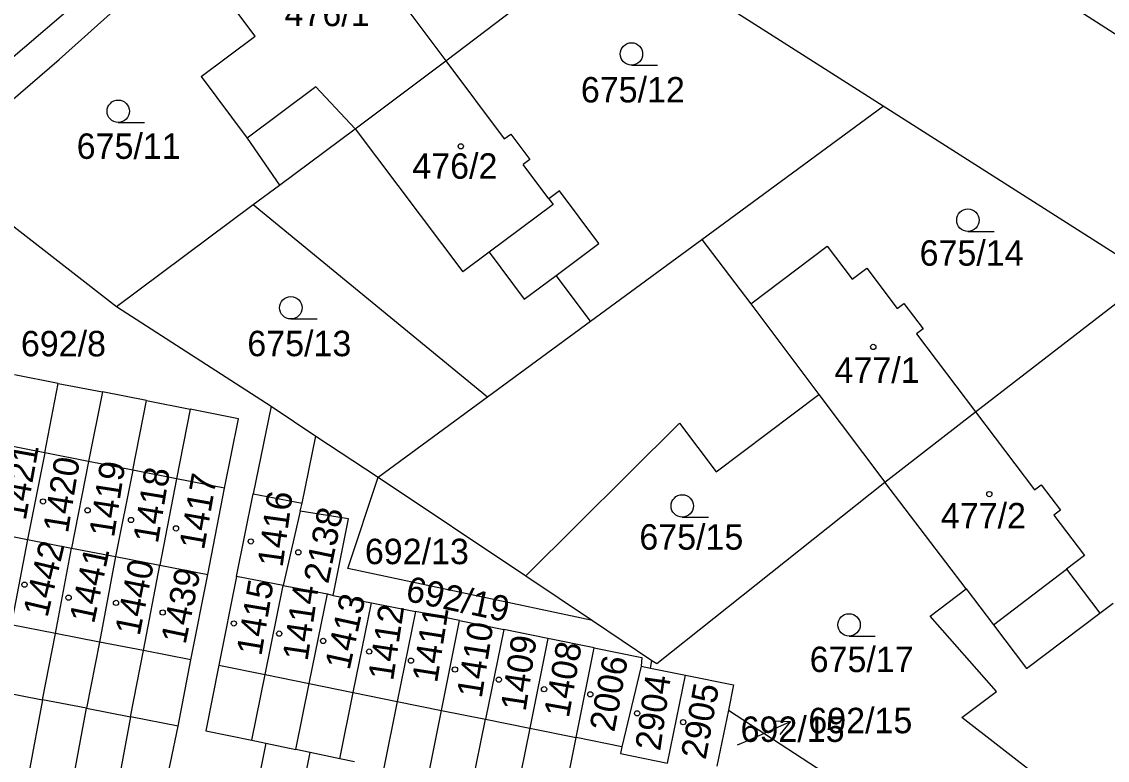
# Model space of a CAD drawing. Extents: x -735249 to -729401, y -1124843 to -1121828.
# Drawn here: x -734390.6 to -734318, y -1123657.3 to -1123607.9 of the extents above; entities that cross this region are included whole.
import ezdxf

# ---------------------------------------------------------------- set-up
doc = ezdxf.new("R2010")
doc.units = 0
for name, color, linetype in [('Vrstva 1', 7, 'Continuous'), ('Vrstva 16', 7, 'Continuous'), ('Vrstva 18', 7, 'Continuous'), ('Vrstva 19', 7, 'Continuous'), ('Vrstva 25', 7, 'Continuous'), ('Vrstva 4', 7, 'Continuous')]:
    doc.layers.add(name, color=color, linetype=linetype)

msp = doc.modelspace()

# ---------------------------------------------------------------- linework, layer by layer
at = {"layer": 'Vrstva 1'}
for points in [[(-734362.22, -1123610.52), (-734351.05, -1123602.02)], [(-734332.98, -1123613.55), (-734351.05, -1123602.02)], [(-734328.07, -1123601.9), (-734302.47, -1123618.32)], [(-734388.08, -1123610.43), (-734379.53, -1123602.76)], [(-734374.96, -1123608.88), (-734379.53, -1123602.76)], [(-734385.93, -1123605.8), (-734391.93, -1123610.94)], [(-734366.1, -1123605.32), (-734362.22, -1123610.52)], [(-734378.57, -1123611.57), (-734374.96, -1123608.88)], [(-734396.34, -1123617.53), (-734388.08, -1123610.43)], [(-734368.28, -1123615.06), (-734362.22, -1123610.52)], [(-734362.22, -1123610.52), (-734358.32, -1123615.74)], [(-734378.57, -1123611.57), (-734375.5, -1123615.68)], [(-734345.11, -1123622.46), (-734332.98, -1123613.55)], [(-734315.08, -1123624.94), (-734332.98, -1123613.55)], [(-734373.34, -1123618.83), (-734368.28, -1123615.06)], [(-734375.5, -1123615.68), (-734373.34, -1123618.83)], [(-734358.32, -1123615.74), (-734357.88, -1123615.41)], [(-734357.88, -1123615.41), (-734356.61, -1123617.11)], [(-734356.61, -1123617.11), (-734357.05, -1123617.44)], [(-734355.34, -1123619.74), (-734357.05, -1123617.44)], [(-734396.34, -1123617.53), (-734384.23, -1123626.94)], [(-734375.09, -1123620.13), (-734373.34, -1123618.83)], [(-734354.62, -1123619.2), (-734355.34, -1123619.74)], [(-734351.98, -1123622.72), (-734354.62, -1123619.2)], [(-734384.23, -1123626.94), (-734375.09, -1123620.13)], [(-734375.09, -1123620.13), (-734359.43, -1123632.97)], [(-734352.55, -1123627.92), (-734345.11, -1123622.46)], [(-734345.11, -1123622.46), (-734341.83, -1123626.76)], [(-734354.85, -1123624.86), (-734351.98, -1123622.72)], [(-734341.83, -1123626.76), (-734336.73, -1123622.9)], [(-734336.73, -1123622.9), (-734335.05, -1123625.12)], [(-734335.05, -1123625.12), (-734334.07, -1123624.38)], [(-734334.07, -1123624.38), (-734332.04, -1123627.07)], [(-734352.55, -1123627.92), (-734354.85, -1123624.86)], [(-734326.8, -1123633.98), (-734315.08, -1123624.94)], [(-734332.04, -1123627.07), (-734331.59, -1123626.73)], [(-734331.59, -1123626.73), (-734330.31, -1123628.43)], [(-734384.23, -1123626.94), (-734373.9, -1123633.6)], [(-734359.43, -1123632.97), (-734352.55, -1123627.92)], [(-734330.31, -1123628.43), (-734330.75, -1123628.77)], [(-734330.75, -1123628.77), (-734326.8, -1123633.98)], [(-734388.13, -1123632.08), (-734391.06, -1123631.5)], [(-734389.04, -1123636.72), (-734388.13, -1123632.08)], [(-734388.13, -1123632.08), (-734385.18, -1123632.65)], [(-734385.18, -1123632.65), (-734386.1, -1123637.29)], [(-734382.24, -1123633.23), (-734385.18, -1123632.65)], [(-734383.15, -1123637.87), (-734382.24, -1123633.23)], [(-734382.24, -1123633.23), (-734379.31, -1123633.81)], [(-734366.75, -1123638.34), (-734359.43, -1123632.97)], [(-734344.15, -1123637.98), (-734337.28, -1123632.81)], [(-734337.28, -1123632.81), (-734332.86, -1123638.67)], [(-734379.31, -1123633.81), (-734380.22, -1123638.45)], [(-734376.09, -1123634.44), (-734379.31, -1123633.81)], [(-734373.9, -1123633.6), (-734375.11, -1123639.45)], [(-734373.9, -1123633.6), (-734370.9, -1123635.6)], [(-734332.86, -1123638.67), (-734326.8, -1123633.98)], [(-734326.8, -1123633.98), (-734322.85, -1123639.19)], [(-734377.01, -1123639.08), (-734376.09, -1123634.44)], [(-734356.88, -1123644.94), (-734346.6, -1123634.73)], [(-734346.6, -1123634.73), (-734344.15, -1123637.98)], [(-734371.83, -1123640.08), (-734370.9, -1123635.6)], [(-734370.9, -1123635.6), (-734366.75, -1123638.34)], [(-734389.04, -1123636.72), (-734390.18, -1123642.51)], [(-734386.1, -1123637.29), (-734387.24, -1123643.08)], [(-734383.15, -1123637.87), (-734384.3, -1123643.65)], [(-734380.22, -1123638.45), (-734381.35, -1123644.22)], [(-734368.78, -1123644.44), (-734366.75, -1123638.34)], [(-734366.75, -1123638.34), (-734356.88, -1123644.94)], [(-734378.14, -1123644.84), (-734377.01, -1123639.08)], [(-734348.11, -1123650.81), (-734332.86, -1123638.67)], [(-734327.43, -1123645.81), (-734332.86, -1123638.67)], [(-734322.85, -1123639.19), (-734322.41, -1123638.85)], [(-734322.41, -1123638.85), (-734321.13, -1123640.55)], [(-734376.21, -1123644.99), (-734375.11, -1123639.45)], [(-734371.95, -1123640.61), (-734373.09, -1123645.58)], [(-734371.95, -1123640.61), (-734371.83, -1123640.08)], [(-734368.73, -1123641.13), (-734371.95, -1123640.61)], [(-734321.13, -1123640.55), (-734321.57, -1123640.89)], [(-734369.76, -1123646.25), (-734368.73, -1123641.13)], [(-734321.57, -1123640.89), (-734319.52, -1123643.59)], [(-734393.11, -1123641.94), (-734390.18, -1123642.51)], [(-734390.18, -1123642.51), (-734391.28, -1123648.22)], [(-734390.18, -1123642.51), (-734387.24, -1123643.08)], [(-734388.32, -1123648.8), (-734387.24, -1123643.08)], [(-734387.24, -1123643.08), (-734384.3, -1123643.65)], [(-734384.3, -1123643.65), (-734385.38, -1123649.37)], [(-734384.3, -1123643.65), (-734381.35, -1123644.22)], [(-734382.44, -1123649.94), (-734381.35, -1123644.22)], [(-734381.35, -1123644.22), (-734378.14, -1123644.84)], [(-734319.52, -1123643.59), (-734320.72, -1123644.5)], [(-734379.26, -1123650.56), (-734378.14, -1123644.84)], [(-734376.21, -1123644.99), (-734377.39, -1123650.92)], [(-734373.09, -1123645.58), (-734376.21, -1123644.99)], [(-734352.41, -1123647.93), (-734368.78, -1123644.44)], [(-734356.88, -1123644.94), (-734352.41, -1123647.93)], [(-734320.72, -1123644.5), (-734318.5, -1123647.43)], [(-734374.3, -1123651.54), (-734373.09, -1123645.58)], [(-734373.09, -1123645.58), (-734370.14, -1123646.14)], [(-734371.36, -1123652.14), (-734370.14, -1123646.14)], [(-734370.14, -1123646.14), (-734369.76, -1123646.25)], [(-734369.76, -1123646.25), (-734367.19, -1123646.74)], [(-734329.83, -1123647.63), (-734327.43, -1123645.81)], [(-734368.41, -1123652.73), (-734367.19, -1123646.74)], [(-734367.19, -1123646.74), (-734364.25, -1123647.33)], [(-734318.5, -1123647.43), (-734317.61, -1123646.76)], [(-734364.25, -1123647.33), (-734365.47, -1123653.33)], [(-734361.3, -1123647.93), (-734364.25, -1123647.33)], [(-734362.51, -1123653.93), (-734361.3, -1123647.93)], [(-734361.3, -1123647.93), (-734358.35, -1123648.53)], [(-734352.41, -1123647.93), (-734348.44, -1123650.59)], [(-734325.41, -1123652.66), (-734329.83, -1123647.63)], [(-734358.35, -1123648.53), (-734359.56, -1123654.53)], [(-734355.4, -1123649.13), (-734358.35, -1123648.53)], [(-734389.18, -1123653.22), (-734388.32, -1123648.8)], [(-734385.38, -1123649.37), (-734386.24, -1123653.79)], [(-734355.4, -1123649.13), (-734356.61, -1123655.12)], [(-734352.3, -1123649.76), (-734355.4, -1123649.13)], [(-734383.31, -1123654.37), (-734382.44, -1123649.94)], [(-734353.5, -1123655.75), (-734352.3, -1123649.76)], [(-734352.3, -1123649.76), (-734349.12, -1123650.4)], [(-734380.12, -1123654.98), (-734379.26, -1123650.56)], [(-734349.12, -1123650.4), (-734349.15, -1123650.97)], [(-734348.53, -1123651.1), (-734348.44, -1123650.59)], [(-734348.44, -1123650.59), (-734348.11, -1123650.81)], [(-734377.39, -1123650.92), (-734378.26, -1123655.29)], [(-734375.2, -1123655.93), (-734374.3, -1123651.54)], [(-734349.15, -1123650.97), (-734350.45, -1123656.37)], [(-734349.15, -1123650.97), (-734348.53, -1123651.1)], [(-734348.53, -1123651.1), (-734346.2, -1123651.57)], [(-734372.25, -1123656.55), (-734371.36, -1123652.14)], [(-734347.4, -1123657.45), (-734346.2, -1123651.57)], [(-734346.2, -1123651.57), (-734342.98, -1123652.22)], [(-734342.98, -1123652.22), (-734343.32, -1123653.92)], [(-734392.14, -1123652.65), (-734389.18, -1123653.22)], [(-734369.3, -1123657.16), (-734368.41, -1123652.73)], [(-734327.71, -1123654.4), (-734325.41, -1123652.66)], [(-734389.18, -1123653.22), (-734390.1, -1123658.14)], [(-734386.24, -1123653.79), (-734389.18, -1123653.22)], [(-734365.47, -1123653.33), (-734366.37, -1123657.78)], [(-734387.16, -1123658.71), (-734386.24, -1123653.79)], [(-734386.24, -1123653.79), (-734383.31, -1123654.37)], [(-734383.31, -1123654.37), (-734384.22, -1123659.29)], [(-734380.12, -1123654.98), (-734383.31, -1123654.37)], [(-734363.41, -1123658.4), (-734362.51, -1123653.93)], [(-734343.32, -1123653.92), (-734344.09, -1123657.67)], [(-734343.32, -1123653.92), (-734329.06, -1123663.2)], [(-734319.82, -1123660.53), (-734327.71, -1123654.4)], [(-734381.14, -1123659.89), (-734380.12, -1123654.98)], [(-734360.47, -1123659.01), (-734359.56, -1123654.53)], [(-734356.61, -1123655.12), (-734357.52, -1123659.63)], [(-734378.26, -1123655.29), (-734375.2, -1123655.93)], [(-734354.41, -1123660.28), (-734353.5, -1123655.75)], [(-734350.45, -1123656.37), (-734353.5, -1123655.75)], [(-734374.25, -1123656.13), (-734375.24, -1123661.04)], [(-734375.2, -1123655.93), (-734374.25, -1123656.13)], [(-734374.25, -1123656.13), (-734372.25, -1123656.55)], [(-734371.29, -1123656.75), (-734372.25, -1123656.55)], [(-734350.45, -1123656.37), (-734350.54, -1123656.81)], [(-734372.26, -1123661.63), (-734371.29, -1123656.75)], [(-734369.3, -1123657.16), (-734371.29, -1123656.75)], [(-734368.33, -1123657.37), (-734369.3, -1123657.16)], [(-734350.54, -1123656.81), (-734347.4, -1123657.45)]]:
    msp.add_lwpolyline(points, dxfattribs=at)
at = {"layer": 'Vrstva 16'}
msp.add_lwpolyline([(-734342.71, -1123656.24), (-734341.92, -1123655.89)], dxfattribs=at)
at = {"layer": 'Vrstva 25'}
for points in [[(-734349.81, -1123610.81), (-734348.06, -1123610.81)], [(-734384.12, -1123614.64), (-734382.37, -1123614.64)], [(-734327.31, -1123621.92), (-734325.56, -1123621.92)], [(-734372.58, -1123627.77), (-734370.83, -1123627.77)], [(-734346.41, -1123641.02), (-734344.66, -1123641.02)], [(-734335.26, -1123648.97), (-734333.51, -1123648.97)], [(-734341.92, -1123655.89), (-734339.176, -1123654.68)], [(-734340.292, -1123654.626), (-734339.176, -1123654.68), (-734339.889, -1123655.541)]]:
    msp.add_lwpolyline(points, dxfattribs=at)
for centre, radius in [((-734349.81, -1123610.06), 0.75), ((-734384.12, -1123613.89), 0.75), ((-734361.22, -1123616.23), 0.175), ((-734327.31, -1123621.17), 0.75), ((-734372.58, -1123627.02), 0.75), ((-734333.64, -1123629.64), 0.175), ((-734389.15, -1123639.97), 0.175), ((-734346.41, -1123640.27), 0.75), ((-734325.88, -1123639.48), 0.175), ((-734386.17, -1123640.56), 0.175), ((-734383.27, -1123641.21), 0.175), ((-734380.26, -1123641.77), 0.175), ((-734375.26, -1123642.64), 0.175), ((-734372.08, -1123643.37), 0.175), ((-734390.39, -1123645.53), 0.175), ((-734387.44, -1123646.4), 0.175), ((-734384.27, -1123646.75), 0.175), ((-734381.15, -1123647.39), 0.175), ((-734335.26, -1123648.22), 0.75), ((-734376.39, -1123648.12), 0.175), ((-734373.36, -1123648.8), 0.175), ((-734370.42, -1123649.29), 0.175), ((-734367.34, -1123650), 0.175), ((-734364.55, -1123650.61), 0.175), ((-734361.61, -1123651.2), 0.175), ((-734358.68, -1123651.88), 0.175), ((-734355.65, -1123652.52), 0.175), ((-734352.56, -1123652.86), 0.175), ((-734349.43, -1123654.13), 0.175), ((-734346.35, -1123654.72), 0.175)]:
    msp.add_circle(centre, radius, dxfattribs=at)
at = {"layer": 'Vrstva 4'}
for points in [[(-734370.91, -1123612.25), (-734375.5, -1123615.68)], [(-734368.28, -1123615.06), (-734370.91, -1123612.25)], [(-734368.28, -1123615.06), (-734361.09, -1123624.63)], [(-734355.05, -1123620.12), (-734359.31, -1123623.3)], [(-734355.34, -1123619.74), (-734355.05, -1123620.12)], [(-734359.31, -1123623.3), (-734361.09, -1123624.63)], [(-734359.31, -1123623.3), (-734356.97, -1123626.44)], [(-734356.97, -1123626.44), (-734354.85, -1123624.86)], [(-734341.83, -1123626.76), (-734337.28, -1123632.81)], [(-734389.04, -1123636.72), (-734391.98, -1123636.14)], [(-734386.1, -1123637.29), (-734389.04, -1123636.72)], [(-734383.15, -1123637.87), (-734386.1, -1123637.29)], [(-734380.22, -1123638.45), (-734383.15, -1123637.87)], [(-734377.01, -1123639.08), (-734380.22, -1123638.45)], [(-734375.11, -1123639.45), (-734371.83, -1123640.08)], [(-734325.61, -1123648.21), (-734320.72, -1123644.5)], [(-734327.43, -1123645.81), (-734325.61, -1123648.21)], [(-734323.39, -1123651.13), (-734318.5, -1123647.43)], [(-734388.32, -1123648.8), (-734391.28, -1123648.22)], [(-734325.61, -1123648.21), (-734323.39, -1123651.13)], [(-734385.38, -1123649.37), (-734388.32, -1123648.8)], [(-734382.44, -1123649.94), (-734385.38, -1123649.37)], [(-734379.26, -1123650.56), (-734382.44, -1123649.94)], [(-734377.39, -1123650.92), (-734374.3, -1123651.54)], [(-734374.3, -1123651.54), (-734371.36, -1123652.14)], [(-734371.36, -1123652.14), (-734368.41, -1123652.73)], [(-734368.41, -1123652.73), (-734365.47, -1123653.33)], [(-734365.47, -1123653.33), (-734362.51, -1123653.93)], [(-734362.51, -1123653.93), (-734359.56, -1123654.53)], [(-734359.56, -1123654.53), (-734356.61, -1123655.12)], [(-734356.61, -1123655.12), (-734353.5, -1123655.75)]]:
    msp.add_lwpolyline(points, dxfattribs=at)

# ---------------------------------------------------------------- texts
at = {"layer": 'Vrstva 16'}
msp.add_text('692/15', height=1.7, dxfattribs=at).set_placement((-734337.98, -1123655.46))
at = {"layer": 'Vrstva 18'}
for s, p in [('675/12', (-734353.19, -1123613.3)), ('675/11', (-734386.9, -1123617.07)), ('675/14', (-734330.54, -1123624.21)), ('692/8', (-734390.63, -1123630.27)), ('675/13', (-734375.49, -1123630.26)), ('675/15', (-734349.28, -1123643.19)), ('692/13', (-734367.63, -1123644.16)), ('675/17', (-734337.89, -1123651.37)), ('692/15', (-734342.51, -1123656.04))]:
    msp.add_text(s, height=1.7, dxfattribs=at).set_placement(p)
msp.add_text('692/19', height=1.7, rotation=348.00277, dxfattribs=at).set_placement((-734364.983, -1123646.596))
at = {"layer": 'Vrstva 19'}
for s, p in [('476/1', (-734373, -1123608.2)), ('476/2', (-734364.46, -1123618.4)), ('477/1', (-734336.23, -1123632.04)), ('477/2', (-734329.12, -1123641.77))]:
    msp.add_text(s, height=1.7, dxfattribs=at).set_placement(p)
for s, rotation, p in [('1421', 79.90064, (-734390.311, -1123641.289)), ('1420', 80.80064, (-734387.485, -1123642.141)), ('1419', 81.20064, (-734384.407, -1123642.422)), ('1418', 80.60064, (-734381.474, -1123642.831)), ('1417', 79.90064, (-734378.391, -1123643.259)), ('1416', 82.10065, (-734373.14, -1123644.415)), ('2138', 78.40062, (-734370.085, -1123645.524)), ('1442', 76.70061, (-734388.858, -1123647.78)), ('1441', 78.10062, (-734385.744, -1123648.194)), ('1440', 78.80063, (-734382.697, -1123649.005)), ('1439', 78.30062, (-734379.625, -1123649.574)), ('1415', 80.50064, (-734374.554, -1123650.34)), ('1414', 81.50065, (-734371.468, -1123650.683)), ('1413', 77.70062, (-734368.662, -1123651.302)), ('1412', 81.40065, (-734365.747, -1123652.003)), ('1411', 81.10064, (-734362.806, -1123652.142)), ('1410', 80.90064, (-734359.825, -1123653.171)), ('1409', 81.30065, (-734356.887, -1123654.053)), ('1408', 79.90064, (-734354.001, -1123654.489)), ('2006', 79.40063, (-734350.959, -1123655.427)), ('2904', 81.80065, (-734347.889, -1123656.694)), ('2905', 79.60063, (-734344.85, -1123657.278))]:
    msp.add_text(s, height=1.7, rotation=rotation, dxfattribs=at).set_placement(p)

doc.saveas('drawing.dxf')
